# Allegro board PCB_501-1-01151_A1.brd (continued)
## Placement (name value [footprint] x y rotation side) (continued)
NOREF#809  -  []  20.17 22.21 0 top
NOREF#810  -  []  57.36 80.33 0 top
NOREF#811  -  []  78.21 22.1 0 top
NOREF#812  -  []  78.21 34.01 0 top
NOREF#813  -  []  78.85 64.66 0 top
NOREF#814  -  []  17.76 81.77 0 top
NOREF#815  -  []  14.08 74.55 0 top
NOREF#816  -  []  97.52 24.96 0 top
NOREF#817  -  []  29.82 76.73 0 top
NOREF#818  -  []  76.58 13.82 90 top
NOREF#819  -  []  50.78 66.44 0 top
NOREF#820  -  []  63.48 71.63 0 top
NOREF#821  -  []  96.9 42.91 90 top
NOREF#822  -  []  90.93 28.17 90 top
NOREF#823  -  []  6.22 53.6 90 top
NOREF#824  -  []  24.24 35.92 0 top
NOREF#825  -  []  36.81 49.93 0 top
NOREF#826  -  []  39.48 69.58 0 top
NOREF#827  -  []  9.02 46.49 90 top
NOREF#828  -  []  61.72 66.02 90 top
NOREF#829  -  []  36.94 20.46 0 top
NOREF#830  -  []  33.51 13.86 0 top
NOREF#831  -  []  73.41 13.82 90 top
NOREF#832  -  []  45.74 35.67 90 top
NOREF#833  -  []  7.35 46.21 0 top
NOREF#834  -  []  7.6 27.96 0 top
NOREF#835  -  []  9.02 44.94 90 top
NOREF#836  -  []  66.27 68.96 0 top
NOREF#837  -  []  67.07 30.71 90 top
NOREF#838  -  []  23.62 54.84 90 top
NOREF#839  -  []  58.27 44.72 0 top
NOREF#840  -  []  40.62 19.41 0 top
NOREF#841  -  []  52.43 40.11 0 top
NOREF#842  -  []  41.07 61.93 0 top
NOREF#843  -  []  63.48 70.49 0 top
NOREF#844  -  []  32.87 11.7 0 top
NOREF#845  -  []  33.51 17.8 0 top
NOREF#846  -  []  33.68 41.67 0 top
NOREF#847  -  []  21.23 39.73 0 top
NOREF#848  -  []  66.82 24.87 90 top
NOREF#849  -  []  22.46 40.64 0 top
NOREF#850  -  []  83.55 63.86 0 top
NOREF#851  -  []  4.04 48.12 0 top
NOREF#852  -  []  46.46 63.86 0 top
NOREF#853  -  []  51.9 2.33 0 top
NOREF#854  -  []  34.78 20.68 0 top
NOREF#855  -  []  18.75 86.98 90 top
NOREF#856  -  []  81.15 60.05 90 top
NOREF#857  -  []  83.42 68.05 0 top
NOREF#858  -  []  12.04 48.62 0 top
NOREF#859  -  []  66.15 53.11 0 top
NOREF#860  -  []  61.32 9.25 0 top
NOREF#861  -  []  38.1 10.9 90 top
NOREF#862  -  []  90.91 69.09 0 top
NOREF#863  -  []  41.38 10.78 0 top
NOREF#864  -  []  57.89 58.82 0 top
NOREF#865  -  []  77.41 33.01 0 top
NOREF#866  -  []  49.89 23.51 0 top
NOREF#867  -  []  9.89 45.86 0 top
NOREF#868  -  []  54.59 75.8 90 top
NOREF#869  -  []  94.47 83.55 0 top
NOREF#870  -  []  32.87 87.76 0 top
NOREF#871  -  []  62.97 42.16 0 top
NOREF#872  -  []  78.85 64.11 90 top
NOREF#873  -  []  2.27 48.75 0 top
NOREF#874  -  []  10.1 6.43 0 top
NOREF#875  -  []  60.98 46.97 0 top
NOREF#876  -  []  67.67 17.14 0 top
NOREF#877  -  []  77.7 27.16 0 top
NOREF#878  -  []  26.27 51.16 90 top
NOREF#879  -  []  51.41 38.12 0 top
NOREF#880  -  []  35.65 15.16 0 top
NOREF#881  -  []  51 -0.27 90 top
NOREF#882  -  []  83.97 25.41 0 top
NOREF#883  -  []  46.74 63.99 90 top
NOREF#884  -  []  60.38 50.58 90 top
NOREF#885  -  []  59.41 46.97 0 top
NOREF#886  -  []  86.72 28.05 0 top
NOREF#887  -  []  38.37 10.78 0 top
NOREF#888  -  []  94.63 68.94 90 top
NOREF#889  -  []  45.32 30.71 0 top
NOREF#890  -  []  67.91 46.5 0 top
NOREF#891  -  []  50.16 11.28 90 top
NOREF#892  -  []  63.36 71.35 90 top
NOREF#893  -  []  39.26 60.98 0 top
NOREF#894  -  []  58.44 58.82 0 top
NOREF#895  -  []  11.19 40.62 90 top
NOREF#896  -  []  41 59.73 0 top
NOREF#897  -  []  67.2 52.56 90 top
NOREF#898  -  []  72.64 10.01 90 top
NOREF#899  -  []  58.78 6.97 0 top
NOREF#900  -  []  26.27 49.64 0 top
NOREF#901  -  []  83.17 6.24 0 top
NOREF#902  -  []  30.72 39.39 0 top
NOREF#903  -  []  29.82 40.37 0 top
NOREF#904  -  []  33.51 14.71 0 top
NOREF#905  -  []  38.61 69.7 90 top
NOREF#906  -  []  83.55 63.86 90 top
NOREF#907  -  []  50.14 57.29 0 top
NOREF#908  -  []  46.34 18.65 0 top
NOREF#909  -  []  58.41 79.78 90 top
NOREF#910  -  []  29.82 41.42 0 top
NOREF#911  -  []  11.76 101 180 top
NOREF#912  -  []  67.67 26.29 0 top
NOREF#913  -  []  91.19 80.6 0 top
NOREF#914  -  []  49.13 49.28 0 top
NOREF#915  -  []  11.92 59.03 0 top
NOREF#916  -  []  66.37 69.09 90 top
NOREF#917  -  []  30.84 39.12 0 top
NOREF#918  -  []  35.93 83.33 90 top
NOREF#919  -  []  47.22 67.44 0 top
NOREF#920  -  []  59.48 49.02 0 top
NOREF#921  -  []  68.71 13.82 90 top
NOREF#922  -  []  96.79 99.77 0 top
NOREF#923  -  []  56.39 12.81 90 top
NOREF#924  -  []  68.33 75.29 90 top
NOREF#925  -  []  35.79 17.02 0 top
NOREF#926  -  []  81.41 9.63 90 top
NOREF#927  -  []  31.39 69.83 0 top
NOREF#928  -  []  35.67 39.65 0 top
NOREF#929  -  []  77.07 19.03 0 top
NOREF#930  -  []  9.55 41.77 0 top
NOREF#931  -  []  78.5 73.42 0 top
NOREF#932  -  []  -7.08 -7.08 90 top
NOREF#933  -  []  51.31 22.59 90 top
NOREF#934  -  []  56.62 51.58 0 top
NOREF#935  -  []  14.58 8.16 0 top
NOREF#936  -  []  48.28 74.28 0 top
NOREF#937  -  []  11.83 47.48 90 top
NOREF#938  -  []  93.85 52.94 90 top
NOREF#939  -  []  7.62 46.34 90 top
NOREF#940  -  []  52.81 49.26 0 top
NOREF#941  -  []  77.34 12.3 90 top
NOREF#942  -  []  89.92 24.62 90 top
NOREF#943  -  []  8.11 38.61 0 top
NOREF#944  -  []  58.78 8.02 0 top
NOREF#945  -  []  42.04 19.54 90 top
NOREF#946  -  []  46.95 68.81 0 top
NOREF#947  -  []  68.3 72.88 0 top
NOREF#948  -  []  23.75 45.7 90 top
NOREF#949  -  []  107.08 -7.08 90 top
NOREF#950  -  []  83.97 11.42 90 top
NOREF#951  -  []  48.37 28.94 0 top
NOREF#952  -  []  70.34 63.26 0 top
NOREF#953  -  []  67.55 22.58 0 top
NOREF#954  -  []  52.2 67.29 90 top
NOREF#955  -  []  51.92 67.17 0 top
NOREF#956  -  []  32.73 12.43 0 top
NOREF#957  -  []  76.71 57.75 90 top
NOREF#958  -  []  30.97 72.24 0 top
NOREF#959  -  []  65.68 47.48 90 top
NOREF#960  -  []  29.65 73.42 90 top
NOREF#961  -  []  93.69 67.56 0 top
NOREF#962  -  []  83.29 5.97 0 top
NOREF#963  -  []  63.48 16.11 0 top
NOREF#964  -  []  59.69 47.1 90 top
NOREF#965  -  []  54.21 67.04 0 top
NOREF#966  -  []  50.02 66.66 0 top
NOREF#967  -  []  60.66 50.46 0 top
NOREF#968  -  []  61.32 73.05 0 top
NOREF#969  -  []  93.08 88.6 0 top
NOREF#970  -  []  94.13 53.87 0 top
NOREF#971  -  []  78.1 13.82 90 top
NOREF#972  -  []  74.4 67.92 0 top
NOREF#973  -  []  51.79 28.94 0 top
NOREF#974  -  []  33.89 56.65 90 top
NOREF#975  -  []  51.16 35.16 0 top
NOREF#976  -  []  49.3 23.51 0 top
NOREF#977  -  []  50.14 56.24 0 top
NOREF#978  -  []  47.1 67.16 0 top
NOREF#979  -  []  51.03 11.16 0 top
NOREF#980  -  []  54.65 60.06 0 top
NOREF#981  -  []  78.76 15.48 0 top
NOREF#982  -  []  68.3 6.88 0 top
NOREF#983  -  []  35.94 94.47 90 top
NOREF#984  -  []  61.49 19.41 90 top
NOREF#985  -  []  31.73 49.81 0 top
NOREF#986  -  []  50.51 36.36 0 top
NOREF#987  -  []  84.44 -1 0 top
NOREF#988  -  []  90.91 25.54 0 top
NOREF#989  -  []  51.67 62.63 0 top
NOREF#990  -  []  44.81 12.57 0 top
NOREF#991  -  []  18.56 68.72 0 top
NOREF#992  -  []  67.55 16.87 0 top
NOREF#993  -  []  35.04 64.95 0 top
NOREF#994  -  []  66.42 45.07 90 top
NOREF#995  -  []  12.05 59.31 0 top
NOREF#996  -  []  57.68 44.05 0 top
NOREF#997  -  []  31.99 57.28 0 top
NOREF#998  -  []  45.32 65.51 0 top
NOREF#999  -  []  41.4 87.25 90 top
NOREF#1000  -  []  74.55 62.46 90 top
NOREF#1001  -  []  77.07 10.94 0 top
NOREF#1002  -  []  50.29 66.78 90 top
NOREF#1003  -  []  53.69 51.49 90 top
NOREF#1004  -  []  67.91 46.1 0 top
NOREF#1005  -  []  2.75 19.74 90 top
NOREF#1006  -  []  51.67 60.71 0 top
NOREF#1007  -  []  64.5 4.05 0 top
NOREF#1008  -  []  65.89 21.72 0 top
NOREF#1009  -  []  80.24 23 0 top
NOREF#1010  -  []  54.76 8.87 0 top
NOREF#1011  -  []  17.76 82.82 0 top
NOREF#1012  -  []  44.17 25.67 0 top
NOREF#1013  -  []  46.34 59.73 0 top
NOREF#1014  -  []  30.1 75.8 90 top
NOREF#1015  -  []  43.69 68.54 90 top
NOREF#1016  -  []  33.95 71.5 0 top
NOREF#1017  -  []  44.43 32.37 0 top
NOREF#1018  -  []  47.9 43.29 90 top
NOREF#1019  -  []  44.17 23.51 0 top
NOREF#1020  -  []  67.55 26.01 0 top
NOREF#1021  -  []  49 49 0 top
NOREF#1022  -  []  71.88 62.34 90 top
NOREF#1023  -  []  45.59 24.75 90 top
NOREF#1024  -  []  37.1 57.24 90 top
NOREF#1025  -  []  78.1 13.82 90 top
NOREF#1026  -  []  43.43 8.87 90 top
NOREF#1027  -  []  52.81 46.5 0 top
NOREF#1028  -  []  78.09 21.82 90 top
NOREF#1029  -  []  14.08 73.41 0 top
NOREF#1030  -  []  61 35.38 0 top
NOREF#1031  -  []  15.11 48.75 90 top
NOREF#1032  -  []  85.47 64.81 90 top
NOREF#1033  -  []  11.92 53.95 0 top
NOREF#1034  -  []  27.07 82.57 90 top
NOREF#1035  -  []  28.05 16.26 0 top
NOREF#1036  -  []  44.56 47.98 0 top
NOREF#1037  -  []  74.28 73.66 0 top
NOREF#1038  -  []  59.05 7.09 90 top
NOREF#1039  -  []  20.68 46.63 0 top
NOREF#1040  -  []  63.23 67.58 0 top
NOREF#1041  -  []  20.54 52.2 0 top
NOREF#1042  -  []  60.71 47.1 90 top
NOREF#1043  -  []  63.48 69.34 0 top
NOREF#1044  -  []  63.63 4.17 90 top
NOREF#1045  -  []  56.62 50.44 0 top
NOREF#1046  -  []  46.97 43.56 0 top
NOREF#1047  -  []  40.64 64.1 90 top
NOREF#1048  -  []  71.25 94.47 90 top
NOREF#1049  -  []  62.09 43.92 0 top
NOREF#1050  -  []  54.74 62.72 90 top
NOREF#1051  -  []  72.92 12.17 0 top
NOREF#1052  -  []  84.73 29.83 0 top
NOREF#1053  -  []  20.96 45.7 90 top
NOREF#1054  -  []  46.97 12.57 0 top
NOREF#1055  -  []  19.68 11.54 90 top
NOREF#1056  -  []  89.64 57.02 0 top
NOREF#1057  -  []  63.88 6.71 90 top
NOREF#1058  -  []  97.77 43.83 0 top
NOREF#1059  -  []  46.88 17.8 0 top
NOREF#1060  -  []  78.97 63.25 0 top
NOREF#1061  -  []  60.38 52.49 90 top
NOREF#1062  -  []  91.39 100 0 top
NOREF#1063  -  []  15.86 81.05 0 top
NOREF#1064  -  []  36.7 15.16 90 top
NOREF#1065  -  []  73.01 56.77 0 top
NOREF#1066  -  []  4.06 45.45 90 top
NOREF#1067  -  []  59.33 12.68 0 top
NOREF#1068  -  []  93.07 60.85 0 top
NOREF#1069  -  []  10.14 39.48 0 top
NOREF#1070  -  []  95.9 25.13 90 top
NOREF#1071  -  []  15.98 48.62 0 top
NOREF#1072  -  []  8.11 42.16 0 top
NOREF#1073  -  []  59.67 34 0 top
NOREF#1074  -  []  76.31 13.7 0 top
NOREF#1075  -  []  51.92 66.8 0 top
NOREF#1076  -  []  47.39 18.65 90 top
NOREF#1077  -  []  50.04 16.87 90 top
NOREF#1078  -  []  76.81 72.33 0 top
NOREF#1079  -  []  20.72 22.21 0 top
NOREF#1080  -  []  30.72 37.7 90 top
NOREF#1081  -  []  37.45 56.15 0 top
NOREF#1082  -  []  67.42 9.42 0 top
NOREF#1083  -  []  8.57 0.31 0 top
NOREF#1084  -  []  94.72 30.35 0 top
NOREF#1085  -  []  76.86 13.7 0 top
NOREF#1086  -  []  66.4 41.91 0 top
NOREF#1087  -  []  95.74 77.62 0 top
NOREF#1088  -  []  23.35 54.72 0 top
NOREF#1089  -  []  11.92 74.27 90 top
NOREF#1090  -  []  79.33 13.36 90 top
NOREF#1091  -  []  51.69 37.19 90 top
NOREF#1092  -  []  53.09 61.7 90 top
NOREF#1093  -  []  62.21 5.1 0 top
NOREF#1094  -  []  14.86 52.3 90 top
NOREF#1095  -  []  94.98 25.4 0 top
NOREF#1096  -  []  38.97 64.66 0 top
NOREF#1097  -  []  86 29.83 0 top
NOREF#1098  -  []  89.41 21.57 90 top
NOREF#1099  -  []  67.2 69.83 90 top
NOREF#1100  -  []  65.89 25.15 0 top
NOREF#1101  -  []  89.52 58.44 0 top
NOREF#1102  -  []  66.82 21.44 90 top
NOREF#1103  -  []  91.46 25.54 0 top
NOREF#1104  -  []  90.79 68.81 0 top
NOREF#1105  -  []  62.21 40.13 0 top
NOREF#1106  -  []  49.78 74.36 90 top
NOREF#1107  -  []  43.2 37.19 0 top
NOREF#1108  -  []  83.82 80.5 90 top
NOREF#1109  -  []  53.61 36.3 0 top
NOREF#1110  -  []  82.52 80.32 0 top
NOREF#1111  -  []  58.01 38.71 90 top
NOREF#1112  -  []  54.21 65.39 0 top
NOREF#1113  -  []  59.84 7.51 0 top
NOREF#1114  -  []  77.62 19.03 0 top
NOREF#1115  -  []  29.44 86.74 0 top
NOREF#1116  -  []  18.78 53.67 0 top
NOREF#1117  -  []  21.59 22.33 90 top
NOREF#1118  -  []  7.34 47.26 0 top
NOREF#1119  -  []  98.32 43.83 0 top
NOREF#1120  -  []  54.76 6.97 0 top
NOREF#1121  -  []  67.69 8.49 90 top
NOREF#1122  -  []  59.67 37.45 0 top
NOREF#1123  -  []  12.05 72.01 0 top
NOREF#1124  -  []  37.7 63.61 0 top
NOREF#1125  -  []  38.73 46.34 90 top
NOREF#1126  -  []  40.13 32.49 90 top
NOREF#1127  -  []  3.19 6.3 0 top
NOREF#1128  -  []  38.73 60.03 90 top
NOREF#1129  -  []  33.03 70.57 0 top
NOREF#1130  -  []  21.48 50.4 90 top
NOREF#1131  -  []  78.85 66.95 0 top
NOREF#1132  -  []  45.61 49.13 90 top
NOREF#1133  -  []  31.12 69.96 90 top
NOREF#1134  -  []  60.09 39.61 0 top
NOREF#1135  -  []  14.35 36.05 90 top
NOREF#1136  -  []  23.73 84.05 90 top
NOREF#1137  -  []  44.42 64.82 90 top
NOREF#1138  -  []  69.44 30.99 0 top
NOREF#1139  -  []  93.71 69.22 0 top
NOREF#1140  -  []  48.75 11.16 0 top
NOREF#1141  -  []  50.58 71.08 0 top
NOREF#1142  -  []  88.62 20.72 0 top
NOREF#1143  -  []  54.48 7.09 90 top
NOREF#1144  -  []  61.2 42.44 0 top
NOREF#1145  -  []  92.44 52.81 0 top
NOREF#1146  -  []  12.05 61.85 0 top
NOREF#1147  -  []  58.35 15.12 0 top
NOREF#1148  -  []  43.71 8.75 0 top
NOREF#1149  -  []  68.6 22.59 90 top
NOREF#1150  -  []  11.92 74.82 0 top
NOREF#1151  -  []  59.29 7.51 0 top
NOREF#1152  -  []  15.01 22.21 0 top
NOREF#1153  -  []  50.93 29.06 90 top
NOREF#1154  -  []  46.46 75.33 0 top
NOREF#1155  -  []  85.45 29.83 0 top
NOREF#1156  -  []  11.92 56.49 0 top
NOREF#1157  -  []  38.95 54.48 0 top
NOREF#1158  -  []  35.52 24.29 0 top
NOREF#1159  -  []  33.25 29.19 0 top
NOREF#1160  -  []  10.41 41.89 90 top
NOREF#1161  -  []  45.32 24.62 0 top
NOREF#1162  -  []  44.43 33.42 0 top
NOREF#1163  -  []  33.13 41.67 0 top
NOREF#1164  -  []  49.76 72.12 0 top
NOREF#1165  -  []  36.94 50.93 0 top
NOREF#1166  -  []  46.74 65.64 90 top
NOREF#1167  -  []  49.89 25.67 0 top
NOREF#1168  -  []  81.01 25.29 0 top
NOREF#1169  -  []  11.92 64.11 90 top
NOREF#1170  -  []  49.89 12.21 0 top
NOREF#1171  -  []  57.64 6.97 0 top
NOREF#1172  -  []  5.46 38.96 90 top
NOREF#1173  -  []  5.82 26.69 0 top
NOREF#1174  -  []  18.78 53.67 90 top
NOREF#1175  -  []  54.23 44.05 90 top
NOREF#1176  -  []  89.39 27.5 90 top
NOREF#1177  -  []  84.46 28.17 90 top
NOREF#1178  -  []  43.31 22.59 90 top
NOREF#1179  -  []  28.45 75.02 90 top
NOREF#1180  -  []  68.6 21.44 90 top
NOREF#1181  -  []  13.57 41.13 0 top
NOREF#1182  -  []  36.68 64.55 0 top
NOREF#1183  -  []  77.94 71.43 0 top
NOREF#1184  -  []  66.29 19.33 90 top
NOREF#1185  -  []  77.95 73.42 0 top
NOREF#1186  -  []  46.74 74.4 90 top
NOREF#1187  -  []  95.74 77.07 90 top
NOREF#1188  -  []  90.13 67.16 90 top
NOREF#1189  -  []  66.78 50.91 0 top
NOREF#1190  -  []  93.2 63.72 0 top
NOREF#1191  -  []  59.82 39.73 90 top
NOREF#1192  -  []  85.41 33.01 90 top
NOREF#1193  -  []  7.73 27.69 0 top
NOREF#1194  -  []  50.2 59.42 90 top
NOREF#1195  -  []  68.6 26.01 90 top
NOREF#1196  -  []  46.33 17.8 0 top
NOREF#1197  -  []  66.27 71.25 0 top
NOREF#1198  -  []  89.39 29.83 0 top
NOREF#1199  -  []  46.85 43.84 0 top
NOREF#1200  -  []  45.45 56.81 0 top
NOREF#1201  -  []  68.78 101 180 top
NOREF#1202  -  []  15.86 80.5 90 top
NOREF#1203  -  []  17.53 48.75 90 top
NOREF#1204  -  []  60.43 6.58 0 top
NOREF#1205  -  []  61.96 48.15 0 top
NOREF#1206  -  []  70.87 5.95 90 top
NOREF#1207  -  []  91.69 22.86 90 top
NOREF#1208  -  []  44.56 49.13 0 top
NOREF#1209  -  []  12.05 74.55 0 top
NOREF#1210  -  []  66.29 37.06 90 top
NOREF#1211  -  []  71.86 31.48 0 top
NOREF#1212  -  []  53.09 49.38 90 top
NOREF#1213  -  []  33.38 40.24 0 top
NOREF#1214  -  []  51 -1.82 90 top
NOREF#1215  -  []  2.75 22.34 90 top
NOREF#1216  -  []  44.81 19.79 90 top
NOREF#1217  -  []  6.32 86.11 0 top
NOREF#1218  -  []  57.4 44.18 90 top
NOREF#1219  -  []  34.69 35.2 0 top
NOREF#1220  -  []  40.24 10.78 0 top
NOREF#1221  -  []  94.49 59.92 90 top
NOREF#1222  -  []  91.42 87.39 0 top
NOREF#1223  -  []  79.88 25 90 top
NOREF#1224  -  []  17.02 67.8 90 top
NOREF#1225  -  []  33.38 40.24 90 top
NOREF#1226  -  []  90.66 29.83 0 top
NOREF#1227  -  []  84.61 34.01 90 top
NOREF#1228  -  []  53.34 65.51 90 top
NOREF#1229  -  []  73.51 59.58 0 top
NOREF#1230  -  []  17.38 76.09 0 top
NOREF#1231  -  []  37.49 21.45 0 top
NOREF#1232  -  []  77.09 71.41 90 top
NOREF#1233  -  []  94.36 70.34 90 top
NOREF#1234  -  []  45.59 65.64 90 top
NOREF#1235  -  []  11.92 64.66 0 top
NOREF#1236  -  []  52.07 29.06 90 top
NOREF#1237  -  []  52.45 11.28 90 top
NOREF#1238  -  []  33.8 27.29 0 top
NOREF#1239  -  []  77.62 10.94 0 top
NOREF#1240  -  []  60.07 34 90 top
NOREF#1241  -  []  83.29 8.27 0 top
NOREF#1242  -  []  55.13 59.71 90 top
NOREF#1243  -  []  51.1 53.05 0 top
NOREF#1244  -  []  34.68 85.33 0 top
NOREF#1245  -  []  3.32 48.75 90 top
NOREF#1246  -  []  92.82 12.28 0 top
NOREF#1247  -  []  92.3 78.11 0 top
NOREF#1248  -  []  56.5 67.92 90 top
NOREF#1249  -  []  93.83 54.74 0 top
NOREF#1250  -  []  43.16 8.75 0 top
NOREF#1251  -  []  93.08 88.6 0 top
NOREF#1252  -  []  101 91.41 90 top
NOREF#1253  -  []  7.22 42.82 0 top
NOREF#1254  -  []  0 19.47 90 top
NOREF#1255  -  []  24.52 26.67 90 top
NOREF#1256  -  []  51.83 69.08 90 top
NOREF#1257  -  []  94.21 58.42 0 top
NOREF#1258  -  []  37.57 60.98 0 top
NOREF#1259  -  []  45.61 47.99 90 top
NOREF#1260  -  []  4.34 46.37 0 top
NOREF#1261  -  []  46.34 58.13 90 top
NOREF#1262  -  []  45.32 29.99 0 top
NOREF#1263  -  []  78.85 65.26 90 top
NOREF#1264  -  []  48.6 59.82 0 top
NOREF#1265  -  []  67.2 34.78 90 top
NOREF#1266  -  []  22.46 36.97 0 top
NOREF#1267  -  []  87.86 70.61 0 top
NOREF#1268  -  []  59.54 43.54 0 top
NOREF#1269  -  []  10.78 48.75 0 top
NOREF#1270  -  []  34.29 10.78 90 top
NOREF#1271  -  []  44.22 10.78 0 top
NOREF#1272  -  []  11.45 48.62 0 top
NOREF#1273  -  []  94.85 25.12 0 top
NOREF#1274  -  []  27.79 17.38 0 top
NOREF#1275  -  []  82.64 80.04 0 top
NOREF#1276  -  []  67.84 39.48 0 top
NOREF#1277  -  []  35.4 25.16 0 top
NOREF#1278  -  []  5.95 26.42 0 top
NOREF#1279  -  []  58.9 15.12 0 top
NOREF#1280  -  []  53.95 49.26 0 top
NOREF#1281  -  []  90.91 70.23 0 top
NOREF#1282  -  []  56.5 66.78 0 top
NOREF#1283  -  []  43.29 32.37 0 top
NOREF#1284  -  []  81.05 15.48 0 top
NOREF#1285  -  []  56.66 12.68 0 top
NOREF#1286  -  []  74.4 70.99 0 top
NOREF#1287  -  []  33.78 12.93 90 top
NOREF#1288  -  []  34.67 60.05 90 top
NOREF#1289  -  []  48.9 16.87 90 top
NOREF#1290  -  []  49.89 24.62 0 top
NOREF#1291  -  []  84.18 29.83 0 top
NOREF#1292  -  []  41.93 10.78 0 top
NOREF#1293  -  []  79.01 18.65 0 top
NOREF#1294  -  []  70.97 95.39 0 top
NOREF#1295  -  []  22.75 55.77 0 top
NOREF#1296  -  []  84.46 29.95 90 top
NOREF#1297  -  []  37.48 62.95 90 top
NOREF#1298  -  []  73.41 13.82 90 top
NOREF#1299  -  []  43.94 45.3 90 top
NOREF#1300  -  []  87.86 28.05 0 top
NOREF#1301  -  []  55.63 65.51 90 top
NOREF#1302  -  []  11.19 39.48 90 top
NOREF#1303  -  []  85.45 27.5 0 top
NOREF#1304  -  []  52.81 62.63 0 top
NOREF#1305  -  []  61.45 66.95 0 top
NOREF#1306  -  []  101 64 90 top
NOREF#1307  -  []  41.09 56.73 90 top
NOREF#1308  -  []  79.5 4.17 90 top
NOREF#1309  -  []  67.44 5.95 90 top
NOREF#1310  -  []  13.95 73.68 0 top
NOREF#1311  -  []  50.65 82.61 0 top
NOREF#1312  -  []  46.95 69.22 0 top
NOREF#1313  -  []  46.46 25.67 0 top
NOREF#1314  -  []  20.43 50.4 0 top
NOREF#1315  -  []  11.18 48.75 90 top
NOREF#1316  -  []  94.34 61.83 0 top
NOREF#1317  -  []  0.64 36.51 0 top
NOREF#1318  -  []  75.33 13.7 0 top
NOREF#1319  -  []  31.86 49.53 0 top
NOREF#1320  -  []  66.27 52.83 0 top
NOREF#1321  -  []  93.58 53.87 0 top
NOREF#1322  -  []  53.34 29.06 90 top
NOREF#1323  -  []  65.64 51.96 0 top
NOREF#1324  -  []  62.21 44.2 0 top
NOREF#1325  -  []  40.24 11.83 0 top
NOREF#1326  -  []  71.61 63.26 0 top
NOREF#1327  -  []  73.17 32.87 90 top
NOREF#1328  -  []  11.92 61.57 90 top
NOREF#1329  -  []  62.48 10.9 90 top
NOREF#1330  -  []  63.35 62.74 0 top
NOREF#1331  -  []  50.06 49 90 top
NOREF#1332  -  []  42.8 10.9 90 top
NOREF#1333  -  []  27.05 90.91 90 top
NOREF#1334  -  []  74.57 10.94 0 top
NOREF#1335  -  []  72.64 58.65 90 top
NOREF#1336  -  []  74.83 72.41 0 top
NOREF#1337  -  []  5.7 50.42 0 top
NOREF#1338  -  []  71.12 12.3 90 top
NOREF#1339  -  []  53.85 23.35 90 top
NOREF#1340  -  []  64.28 62.46 90 top
NOREF#1341  -  []  23.22 90.44 0 top
NOREF#1342  -  []  51.67 61.58 0 top
NOREF#1343  -  []  32.76 46.3 90 top
NOREF#1344  -  []  70.84 12.17 0 top
NOREF#1345  -  []  78.36 4.17 90 top
NOREF#1346  -  []  65.77 20.3 0 top
NOREF#1347  -  []  7.98 38.33 0 top
NOREF#1348  -  []  5.24 37.06 90 top
NOREF#1349  -  []  76.58 13.82 90 top
NOREF#1350  -  []  76.43 25.38 0 top
NOREF#1351  -  []  94.09 58.7 0 top
NOREF#1352  -  []  66.02 17.14 0 top
NOREF#1353  -  []  32.62 35.2 0 top
NOREF#1354  -  []  67.56 39.6 90 top
NOREF#1355  -  []  59.96 46.97 0 top
NOREF#1356  -  []  36.82 68.62 90 top
NOREF#1357  -  []  47.9 12.3 90 top
NOREF#1358  -  []  37.08 62.95 90 top
NOREF#1359  -  []  76.71 25.51 90 top
NOREF#1360  -  []  24.24 36.97 0 top
NOREF#1361  -  []  76.2 19.16 90 top
NOREF#1362  -  []  56.5 49.38 0 top
NOREF#1363  -  []  67.67 24 0 top
NOREF#1364  -  []  66.95 16.87 90 top
NOREF#1365  -  []  35.29 28.87 90 top
NOREF#1366  -  []  64.77 4.17 90 top
NOREF#1367  -  []  33.95 71.5 0 top
NOREF#1368  -  []  76.71 27.29 90 top
NOREF#1369  -  []  73.13 13.7 0 top
NOREF#1370  -  []  23.86 85.6 0 top
NOREF#1371  -  []  71.61 13.7 0 top
NOREF#1372  -  []  52.81 50.31 0 top
NOREF#1373  -  []  67.67 19.43 0 top
NOREF#1374  -  []  94.6 31.22 0 top
NOREF#1375  -  []  22.14 51.8 90 top
NOREF#1376  -  []  95.14 57 90 top
NOREF#1377  -  []  35.04 62.05 90 top
NOREF#1378  -  []  68.6 28.3 90 top
NOREF#1379  -  []  106.17 104.5 0 top
NOREF#1380  -  []  68.58 5.95 90 top
NOREF#1381  -  []  51.29 56.24 0 top
NOREF#1382  -  []  72.92 59.58 0 top
NOREF#1383  -  []  31.1 72.52 0 top
NOREF#1384  -  []  35.4 24.01 90 top
NOREF#1385  -  []  36.45 25.16 90 top
NOREF#1386  -  []  11.92 69.19 0 top
NOREF#1387  -  []  31.73 37.96 0 top
NOREF#1388  -  []  75.54 12.17 0 top
NOREF#1389  -  []  67.16 6.88 0 top
NOREF#1390  -  []  12.34 43.67 90 top
NOREF#1391  -  []  51.4 83.85 0 top
NOREF#1392  -  []  50.65 29.99 0 top
NOREF#1393  -  []  74.28 69.45 90 top
NOREF#1394  -  []  57.04 7.09 0 top
NOREF#1395  -  []  55.35 8.87 0 top
NOREF#1396  -  []  18.16 71.62 90 top
NOREF#1397  -  []  57.39 6.2 0 top
NOREF#1398  -  []  52.81 45.45 0 top
NOREF#1399  -  []  69.07 9.29 0 top
NOREF#1400  -  []  35.4 24.56 0 top
NOREF#1401  -  []  78.85 67.54 90 top
NOREF#1402  -  []  62.25 41.89 90 top
NOREF#1403  -  []  65.89 24 0 top
NOREF#1404  -  []  42.18 48.4 0 top
NOREF#1405  -  []  38.33 61.63 0 top
NOREF#1406  -  []  75.06 13.82 90 top
NOREF#1407  -  []  37.36 50.65 0 top
NOREF#1408  -  []  73.01 82.61 0 top
NOREF#1409  -  []  38.95 54.08 90 top
NOREF#1410  -  []  66.15 49.76 90 top
NOREF#1411  -  []  78.85 66.4 90 top
NOREF#1412  -  []  53.57 23.22 0 top
NOREF#1413  -  []  77.7 28.21 0 top
NOREF#1414  -  []  45.32 66.57 0 top
NOREF#1415  -  []  42.91 56.3 0 top
NOREF#1416  -  []  76.37 23.22 0 top
NOREF#1417  -  []  57.3 58.82 0 top
NOREF#1418  -  []  46.46 23.51 0 top
NOREF#1419  -  []  21.31 22.21 0 top
NOREF#1420  -  []  35.52 25.43 0 top
NOREF#1421  -  []  52.81 43.92 0 top
NOREF#1422  -  []  62.09 39.86 90 top
NOREF#1423  -  []  32.87 89.03 0 top
NOREF#1424  -  []  65.77 22.58 0 top
NOREF#1425  -  []  55.63 9 90 top
NOREF#1426  -  []  20.68 45.58 0 top
NOREF#1427  -  []  89.14 81.05 0 top
NOREF#1428  -  []  78.85 65.81 0 top
NOREF#1429  -  []  87.74 70.34 0 top
NOREF#1430  -  []  44.94 10.8 0 top
NOREF#1431  -  []  66.82 20.3 90 top
NOREF#1432  -  []  67.55 19.16 0 top
NOREF#1433  -  []  32.93 71.6 0 top
NOREF#1434  -  []  76.43 26.43 0 top
NOREF#1435  -  []  67.2 68.69 90 top
NOREF#1436  -  []  14.31 38.86 0 top
NOREF#1437  -  []  56.62 50.8 0 top
NOREF#1438  -  []  33.53 27.41 90 top
NOREF#1439  -  []  42.14 32.37 0 top
NOREF#1440  -  []  51.33 66.44 0 top
NOREF#1441  -  []  78.49 15.6 90 top
NOREF#1442  -  []  68.05 75.17 0 top
NOREF#1443  -  []  28.93 84.64 0 top
NOREF#1444  -  []  94.12 81.26 90 top
NOREF#1445  -  []  79.36 12.72 0 top
NOREF#1446  -  []  80.52 22.08 90 top
NOREF#1447  -  []  44.81 10.52 0 top
NOREF#1448  -  []  81.32 84.2 0 top
NOREF#1449  -  []  23.73 85.32 0 top
NOREF#1450  -  []  47.01 65.16 0 top
NOREF#1451  -  []  51.58 11.16 0 top
NOREF#1452  -  []  12.97 53.95 90 top
NOREF#1453  -  []  67.2 70.97 90 top
NOREF#1454  -  []  28.85 75.02 0 top
NOREF#1455  -  []  72.12 33.42 0 top
NOREF#1456  -  []  53.85 25.51 90 top
NOREF#1457  -  []  20.68 39.73 0 top
NOREF#1458  -  []  85.48 70.29 0 top
NOREF#1459  -  []  18.16 71.62 90 top
NOREF#1460  -  []  65 53.45 0 top
NOREF#1461  -  []  42.93 37.32 90 top
NOREF#1462  -  []  78.97 67.82 0 top
NOREF#1463  -  []  2.79 39.06 90 top
NOREF#1464  -  []  79.74 60.98 0 top
NOREF#1465  -  []  99.71 105.06 0 top
NOREF#1466  -  []  14.56 38.23 0 top
NOREF#1467  -  []  52.61 69.89 0 top
NOREF#1468  -  []  23.39 40.37 90 top
NOREF#1469  -  []  63.23 62.46 0 top
NOREF#1470  -  []  18.05 11.41 0 top
NOREF#1471  -  []  77.83 13.7 0 top
NOREF#1472  -  []  79.74 57.53 0 top
NOREF#1473  -  []  70.59 6.88 0 top
NOREF#1474  -  []  59.56 4.93 90 top
NOREF#1475  -  []  33.51 15.77 0 top
NOREF#1476  -  []  33.4 40.75 90 top
NOREF#1477  -  []  62.23 54.84 90 top
NOREF#1478  -  []  59.56 6.58 90 top
NOREF#1479  -  []  28.05 41.67 0 top
NOREF#1480  -  []  76.31 74.11 0 top
NOREF#1481  -  []  67.17 26.9 90 top
NOREF#1482  -  []  80.16 24.87 0 top
NOREF#1483  -  []  31.77 38.84 90 top
NOREF#1484  -  []  22.2 55.77 0 top
NOREF#1485  -  []  22.1 45.7 90 top
NOREF#1486  -  []  49.3 11.16 0 top
NOREF#1487  -  []  47.77 29.06 90 top
NOREF#1488  -  []  73.13 14.75 0 top
NOREF#1489  -  []  14.84 49.67 0 top
NOREF#1490  -  []  58.78 12.68 0 top
NOREF#1491  -  []  13.32 81.11 90 top
NOREF#1492  -  []  39.48 70.63 0 top
NOREF#1493  -  []  61.43 18.38 0 top
NOREF#1494  -  []  56.97 41.21 0 top
NOREF#1495  -  []  64.28 63.61 90 top
NOREF#1496  -  []  17.78 11.54 90 top
NOREF#1497  -  []  13.7 41.4 0 top
NOREF#1498  -  []  54.72 76.07 0 top
NOREF#1499  -  []  46.46 65.51 0 top
NOREF#1500  -  []  39.91 63.92 0 top
NOREF#1501  -  []  46.46 18.92 0 top
NOREF#1502  -  []  15.13 53.23 0 top
NOREF#1503  -  []  97.39 38.5 0 top
NOREF#1504  -  []  26.14 82.3 0 top
NOREF#1505  -  []  85.72 28.17 90 top
NOREF#1506  -  []  51.89 70.49 90 top
NOREF#1507  -  []  27.33 91.84 0 top
NOREF#1508  -  []  49.51 29.99 0 top
NOREF#1509  -  []  79.9 15.48 0 top
NOREF#1510  -  []  42.31 22.24 0 top
NOREF#1511  -  []  78.08 5.1 0 top
NOREF#1512  -  []  77.62 12.17 0 top
NOREF#1513  -  []  46.85 12.85 0 top
NOREF#1514  -  []  23.5 29.21 90 top
NOREF#1515  -  []  12.97 69.19 90 top
NOREF#1516  -  []  50.16 24.75 90 top
NOREF#1517  -  []  16.74 68.72 0 top
NOREF#1518  -  []  78.08 4.05 0 top
NOREF#1519  -  []  80.77 15.6 90 top
NOREF#1520  -  []  32.75 87.48 0 top
NOREF#1521  -  []  66.15 69.24 0 top
NOREF#1522  -  []  39.21 67.42 0 top
NOREF#1523  -  []  39.1 11.83 0 top
NOREF#1524  -  []  51.02 58.78 0 top
NOREF#1525  -  []  20.05 43.56 0 top
NOREF#1526  -  []  94.76 60.85 0 top
NOREF#1527  -  []  79.46 13.64 0 top
NOREF#1528  -  []  55.35 65.39 0 top
NOREF#1529  -  []  32.75 89.9 90 top
NOREF#1530  -  []  15.36 92.42 0 top
NOREF#1531  -  []  92.73 86.88 90 top
NOREF#1532  -  []  53.3 53.05 90 top
NOREF#1533  -  []  29.82 75.67 0 top
NOREF#1534  -  []  65.36 19.61 0 top
NOREF#1535  -  []  57.13 44.05 0 top
NOREF#1536  -  []  68.98 13.7 0 top
NOREF#1537  -  []  44.94 75.35 90 top
NOREF#1538  -  []  54.23 49.38 90 top
NOREF#1539  -  []  44.68 49.4 0 top
NOREF#1540  -  []  69.07 9.89 0 top
NOREF#1541  -  []  53.87 11.16 0 top
NOREF#1542  -  []  14.58 53.23 0 top
NOREF#1543  -  []  52.61 16.76 90 top
NOREF#1544  -  []  30.84 37.97 0 top
NOREF#1545  -  []  65.77 21.44 0 top
NOREF#1546  -  []  52.79 57.53 0 top
NOREF#1547  -  []  50.04 72.24 90 top
NOREF#1548  -  []  21.86 22.21 0 top
NOREF#1549  -  []  68.6 24.87 90 top
NOREF#1550  -  []  51.56 56.37 90 top
NOREF#1551  -  []  11.29 43.67 0 top
NOREF#1552  -  []  35.31 83.43 90 top
NOREF#1553  -  []  69.47 62.34 90 top
NOREF#1554  -  []  47.01 23.51 0 top
NOREF#1555  -  []  39.75 69.7 90 top
NOREF#1556  -  []  69.26 31.58 0 top
NOREF#1557  -  []  69.87 12.3 0 top
NOREF#1558  -  []  17.8 48.62 0 top
NOREF#1559  -  []  90.13 67.56 0 top
NOREF#1560  -  []  23.73 84.6 0 top
NOREF#1561  -  []  44.81 33.53 0 top
NOREF#1562  -  []  27.92 15.98 90 top
NOREF#1563  -  []  93.45 68.3 0 top
NOREF#1564  -  []  14.73 22.33 90 top
NOREF#1565  -  []  12.97 59.03 90 top
NOREF#1566  -  []  65.89 20.57 0 top
NOREF#1567  -  []  54.21 68.09 0 top
NOREF#1568  -  []  44.17 65.51 0 top
NOREF#1569  -  []  8.78 30.08 0 top
NOREF#1570  -  []  94.6 30.08 0 top
NOREF#1571  -  []  60.73 18.15 0 top
NOREF#1572  -  []  73.01 82.61 90 top
NOREF#1573  -  []  74.28 70.72 0 top
NOREF#1574  -  []  70 6.88 0 top
NOREF#1575  -  []  65.9 16.87 0 top
NOREF#1576  -  []  35.77 15.43 0 top
NOREF#1577  -  []  81.51 7.37 0 top
NOREF#1578  -  []  91.21 29.83 0 top
NOREF#1579  -  []  63.9 41.89 90 top
NOREF#1580  -  []  76.1 23.35 90 top
NOREF#1581  -  []  54.48 9 90 top
NOREF#1582  -  []  69.07 10.94 0 top
NOREF#1583  -  []  10.27 39.75 0 top
NOREF#1584  -  []  83.89 65.8 90 top
NOREF#1585  -  []  56.87 40.92 0 top
NOREF#1586  -  []  60.11 53.41 0 top
NOREF#1587  -  []  51.05 65.51 90 top
NOREF#1588  -  []  53.07 65.39 0 top
NOREF#1589  -  []  72.64 12.3 90 top
NOREF#1590  -  []  75.92 19.03 0 top
NOREF#1591  -  []  88.14 28.17 90 top
NOREF#1592  -  []  51.92 66.44 0 top
NOREF#1593  -  []  96.76 19.44 90 top
NOREF#1594  -  []  10.9 49.02 0 top
NOREF#1595  -  []  77.83 14.75 0 top
NOREF#1596  -  []  63.48 17.16 0 top
NOREF#1597  -  []  56.49 7.09 0 top
NOREF#1598  -  []  11.92 62.12 0 top
NOREF#1599  -  []  2.39 49.02 0 top
NOREF#1600  -  []  51.56 35.81 90 top
NOREF#1601  -  []  79.99 10.56 0 top
NOREF#1602  -  []  34.02 10.65 0 top
NOREF#1603  -  []  62.76 10.78 0 top
NOREF#1604  -  []  47.6 24.62 0 top
NOREF#1605  -  []  23.47 46.63 0 top
NOREF#1606  -  []  41 32.37 0 top
NOREF#1607  -  []  84.36 47.44 0 top
NOREF#1608  -  []  89.52 57.3 0 top
NOREF#1609  -  []  14.08 35.92 0 top
NOREF#1610  -  []  61.54 38.03 0 top
NOREF#1611  -  []  62.97 9.25 0 top
NOREF#1612  -  []  73.75 89.53 90 top
NOREF#1613  -  []  77.34 19.16 90 top
NOREF#1614  -  []  37.7 64.66 0 top
NOREF#1615  -  []  76.81 71.28 0 top
NOREF#1616  -  []  77.07 12.17 0 top
NOREF#1617  -  []  47.06 65.79 0 top
NOREF#1618  -  []  67.67 28.58 0 top
NOREF#1619  -  []  61.21 41.24 0 top
NOREF#1620  -  []  71.86 32.53 0 top
NOREF#1621  -  []  10.14 42.82 0 top
NOREF#1622  -  []  50.31 17.8 0 top
NOREF#1623  -  []  33.51 18.65 0 top
NOREF#1624  -  []  34.4 59.93 0 top
NOREF#1625  -  []  74.15 73.39 0 top
NOREF#1626  -  []  49.78 29.06 90 top
NOREF#1627  -  []  90.46 23.59 0 top
NOREF#1628  -  []  71.88 13.82 90 top
NOREF#1629  -  []  65.8 35.54 90 top
NOREF#1630  -  []  67.55 21.44 0 top
NOREF#1631  -  []  2.79 36.96 90 top
NOREF#1632  -  []  5.57 50.14 90 top
NOREF#1633  -  []  48.37 29.99 0 top
NOREF#1634  -  []  42.31 20.46 0 top
NOREF#1635  -  []  7.6 29.36 0 top
NOREF#1636  -  []  91.19 20.68 90 top
NOREF#1637  -  []  51.58 23.51 0 top
NOREF#1638  -  []  67.67 22.86 0 top
NOREF#1639  -  []  30.84 36.83 0 top
NOREF#1640  -  []  12.97 71.73 90 top
NOREF#1641  -  []  95.29 67.16 90 top
NOREF#1642  -  []  73.75 83.85 0 top
NOREF#1643  -  []  10.14 41.77 0 top
NOREF#1644  -  []  32.86 43.97 90 top
NOREF#1645  -  []  94.6 31.22 90 top
NOREF#1646  -  []  63.01 47.6 90 top
NOREF#1647  -  []  32.78 49.25 90 top
NOREF#1648  -  []  67.67 27.43 0 top
NOREF#1649  -  []  12.32 48.75 90 top
NOREF#1650  -  []  83.69 68.18 90 top
NOREF#1651  -  []  57.33 40.07 90 top
NOREF#1652  -  []  55.35 7.09 0 top
NOREF#1653  -  []  33.53 25.63 90 top
NOREF#1654  -  []  30.72 37.7 0 top
NOREF#1655  -  []  36.72 40.24 90 top
NOREF#1656  -  []  75.09 27.18 90 top
NOREF#1657  -  []  81.39 7.09 90 top
NOREF#1658  -  []  55.13 59.71 0 top
NOREF#1659  -  []  57.02 65.51 90 top
NOREF#1660  -  []  57.02 57.89 90 top
NOREF#1661  -  []  90.97 80.4 0 top
NOREF#1662  -  []  53.32 11.16 0 top
NOREF#1663  -  []  73.97 27.89 0 top
NOREF#1664  -  []  38.12 60.98 0 top
NOREF#1665  -  []  68.6 27.16 90 top
NOREF#1666  -  []  28.07 17.51 90 top
NOREF#1667  -  []  60.43 19.96 0 top
NOREF#1668  -  []  74.27 63.39 0 top
NOREF#1669  -  []  67.16 5.82 0 top
NOREF#1670  -  []  10.54 53.15 90 top
NOREF#1671  -  []  79.48 12.45 0 top
NOREF#1672  -  []  41.63 48.4 0 top
NOREF#1673  -  []  77.45 23.48 0 top
NOREF#1674  -  []  34.91 20.96 0 top
NOREF#1675  -  []  56.75 66.44 0 top
NOREF#1676  -  []  91.04 83.08 0 top
NOREF#1677  -  []  69.83 72.88 0 top
NOREF#1678  -  []  30.2 84.09 0 top
NOREF#1679  -  []  93.06 100.21 0 top
NOREF#1680  -  []  62.85 42.44 0 top
NOREF#1681  -  []  33.38 39.65 0 top
NOREF#1682  -  []  33.38 84.35 0 top
NOREF#1683  -  []  20.43 48.62 0 top
NOREF#1684  -  []  76.31 57.75 90 top
NOREF#1685  -  []  50.63 36.09 0 top
NOREF#1686  -  []  40.46 63.64 0 top
NOREF#1687  -  []  26.27 49.64 90 top
NOREF#1688  -  []  89.77 20.72 0 top
NOREF#1689  -  []  76.56 21.06 0 top
NOREF#1690  -  []  31.34 -1 0 top
NOREF#1691  -  []  58.44 6.2 90 top
NOREF#1692  -  []  36.22 95.39 0 top
NOREF#1693  -  []  -1 78.29 270 top
NOREF#1694  -  []  -1 8.08 270 top
NOREF#1695  -  []  26.89 6.43 90 top
NOREF#1696  -  []  77.34 15.6 90 top
NOREF#1697  -  []  67.55 28.3 0 top
NOREF#1698  -  []  66.7 39.48 0 top
NOREF#1699  -  []  33.51 19.7 0 top
NOREF#1700  -  []  76.82 84.2 0 top
NOREF#1701  -  []  16.26 48.75 90 top
NOREF#1702  -  []  55.01 63.64 0 top
NOREF#1703  -  []  79.61 19.7 0 top
NOREF#1704  -  []  48.75 23.51 0 top
NOREF#1705  -  []  66.15 43.96 0 top
NOREF#1706  -  []  16.41 92.42 90 top
NOREF#1707  -  []  7.98 37.19 0 top
NOREF#1708  -  []  72.37 10.94 0 top
NOREF#1709  -  []  61.87 9.25 0 top
NOREF#1710  -  []  36.72 16.74 90 top
NOREF#1711  -  []  51.41 37.07 0 top
NOREF#1712  -  []  52.18 11.16 0 top
NOREF#1713  -  []  87.74 70.34 90 top
NOREF#1714  -  []  71.61 62.21 0 top
NOREF#1715  -  []  41.07 55.93 90 top
NOREF#1716  -  []  53.57 41.17 0 top
NOREF#1717  -  []  39.1 62.59 90 top
NOREF#1718  -  []  30.84 69.83 0 top
NOREF#1719  -  []  52.99 51.69 0 top
NOREF#1720  -  []  0.03 36.33 0 top
NOREF#1721  -  []  5.6 19.74 90 top
NOREF#1722  -  []  43.89 75.9 0 top
NOREF#1723  -  []  28.93 84.09 90 top
NOREF#1724  -  []  12.21 45.95 90 top
NOREF#1725  -  []  80.47 21.39 90 top
NOREF#1726  -  []  17.65 75.16 90 top
NOREF#1727  -  []  34.78 20.68 90 top
NOREF#1728  -  []  93.6 60.16 0 top
NOREF#1729  -  []  51.16 74.31 90 top
NOREF#1730  -  []  93.45 71.39 0 top
NOREF#1731  -  []  45.59 22.59 90 top
NOREF#1732  -  []  53.06 66.44 0 top
NOREF#1733  -  []  33.66 83.42 90 top
NOREF#1734  -  []  10.9 48.62 0 top
NOREF#1735  -  []  66.37 65.59 0 top
NOREF#1736  -  []  53.8 35.38 0 top
NOREF#1737  -  []  71.26 32.66 90 top
NOREF#1738  -  []  67.33 41.63 90 top
NOREF#1739  -  []  81.68 9.51 0 top
NOREF#1740  -  []  91.92 22.63 90 top
NOREF#1741  -  []  18.29 67.8 90 top
NOREF#1742  -  []  5.57 50.14 0 top
NOREF#1743  -  []  33.53 29.32 90 top
NOREF#1744  -  []  94.47 18.14 0 top
NOREF#1745  -  []  88.63 19.67 0 top
NOREF#1746  -  []  30.59 39.01 0 top
NOREF#1747  -  []  2.52 46.37 0 top
NOREF#1748  -  []  91.97 87.39 0 top
NOREF#1749  -  []  34.14 35.2 0 top
NOREF#1750  -  []  90.66 27.5 0 top
NOREF#1751  -  []  84.18 27.5 0 top
NOREF#1752  -  []  50.57 51.69 0 top
NOREF#1753  -  []  43.29 70.14 0 top
NOREF#1754  -  []  77.34 10.01 90 top
NOREF#1755  -  []  80.24 21.95 0 top
NOREF#1756  -  []  83.97 68.05 0 top
NOREF#1757  -  []  63.35 4.05 0 top
NOREF#1758  -  []  29.32 87.02 0 top
NOREF#1759  -  []  56.97 84.2 0 top
NOREF#1760  -  []  70.97 59.58 0 top
NOREF#1761  -  []  79.27 9.51 0 top
NOREF#1762  -  []  89.94 29.83 0 top
NOREF#1763  -  []  24.61 91.69 0 top
NOREF#1764  -  []  61.45 70.21 90 top
NOREF#1765  -  []  88.37 71.74 0 top
NOREF#1766  -  []  64.75 47.75 0 top
NOREF#1767  -  []  63.35 66.17 0 top
NOREF#1768  -  []  94.74 83.67 90 top
NOREF#1769  -  []  11.16 45.95 0 top
NOREF#1770  -  []  66.42 43.03 90 top
NOREF#1771  -  []  90.97 80.4 90 top
NOREF#1772  -  []  61.32 42.16 0 top
NOREF#1773  -  []  56.5 50.53 0 top
NOREF#1774  -  []  12.05 64.39 0 top
NOREF#1775  -  []  6.88 26.14 90 top
NOREF#1776  -  []  62.48 4.17 90 top
NOREF#1777  -  []  36.34 27.6 90 top
NOREF#1778  -  []  46.61 16.87 90 top
NOREF#1779  -  []  56.62 49.89 90 top
NOREF#1780  -  []  45.45 30.99 0 top
NOREF#1781  -  []  51.03 23.51 0 top
NOREF#1782  -  []  54.21 8.87 0 top
NOREF#1783  -  []  21.82 46.63 0 top
NOREF#1784  -  []  42.4 64.03 0 top
NOREF#1785  -  []  7.33 43.96 0 top
NOREF#1786  -  []  53.95 43.92 0 top
NOREF#1787  -  []  93.62 23.09 90 top
NOREF#1788  -  []  62.29 38.78 0 top
NOREF#1789  -  []  41.27 32.49 90 top
NOREF#1790  -  []  39.86 32.37 0 top
NOREF#1791  -  []  45.74 12.3 90 top
NOREF#1792  -  []  17.02 55.35 90 top
NOREF#1793  -  []  65.55 53.45 0 top
NOREF#1794  -  []  45.85 55.21 90 top
NOREF#1795  -  []  32.86 32.75 0 top
NOREF#1796  -  []  15.47 41.4 0 top
NOREF#1797  -  []  52.61 69.89 90 top
NOREF#1798  -  []  71.25 58.65 90 top
NOREF#1799  -  []  53.57 26.43 0 top
NOREF#1800  -  []  69.6 12.43 90 top
NOREF#1801  -  []  94.21 60.85 0 top
NOREF#1802  -  []  37.57 55.88 0 top
NOREF#1803  -  []  50.31 72.12 0 top
NOREF#1804  -  []  67.67 21.72 0 top
NOREF#1805  -  []  93.2 81.53 0 top
NOREF#1806  -  []  67.18 62.34 90 top
NOREF#1807  -  []  23.35 55.77 0 top
NOREF#1808  -  []  68.43 13.7 0 top
NOREF#1809  -  []  30.86 38.08 90 top
NOREF#1810  -  []  67.67 20.57 0 top
NOREF#1811  -  []  34.4 60.98 0 top
NOREF#1812  -  []  61.6 9.38 90 top
NOREF#1813  -  []  35.79 39.37 0 top
NOREF#1814  -  []  31.89 56.65 0 top
NOREF#1815  -  []  65.28 53.57 90 top
NOREF#1816  -  []  62.09 43.92 90 top
NOREF#1817  -  []  54.97 20.3 0 top
NOREF#1818  -  []  15.98 49.67 0 top
NOREF#1819  -  []  51.89 70.49 0 top
NOREF#1820  -  []  83.89 67.4 0 top
NOREF#1821  -  []  89.77 19.67 0 top
NOREF#1822  -  []  66.27 50.04 0 top
NOREF#1823  -  []  33.8 29.19 0 top
NOREF#1824  -  []  57.91 7.09 90 top
NOREF#1825  -  []  68.6 19.16 90 top
NOREF#1826  -  []  40.86 62.04 90 top
NOREF#1827  -  []  63.23 65.89 0 top
NOREF#1828  -  []  27.92 15.98 0 top
NOREF#1829  -  []  36.93 4.58 0 top
NOREF#1830  -  []  5.24 43.46 90 top
NOREF#1831  -  []  35.41 29.15 0 top
NOREF#1832  -  []  89.13 21.45 0 top
NOREF#1833  -  []  72.52 73.01 90 top
NOREF#1834  -  []  90.19 25.54 0 top
NOREF#1835  -  []  73.68 13.7 0 top
NOREF#1836  -  []  74.4 66.78 0 top
NOREF#1837  -  []  50.65 31.77 0 top
NOREF#1838  -  []  83.67 64.13 0 top
NOREF#1839  -  []  61.45 70.76 0 top
NOREF#1840  -  []  68.05 62.21 0 top
NOREF#1841  -  []  79.88 18.78 90 top
NOREF#1842  -  []  97.66 37.57 90 top
NOREF#1843  -  []  92.57 23.09 0 top
NOREF#1844  -  []  8.74 44.81 0 top
NOREF#1845  -  []  8.62 46.44 0 top
NOREF#1846  -  []  76.43 28.21 0 top
NOREF#1847  -  []  112.39 62.91 0 top
NOREF#1848  -  []  78.22 72.5 90 top
NOREF#1849  -  []  49.51 28.94 0 top
NOREF#1850  -  []  50.65 30.72 0 top
NOREF#1851  -  []  63.61 7.64 0 top
NOREF#1852  -  []  45.74 34.52 90 top
NOREF#1853  -  []  5.46 39.61 90 top
NOREF#1854  -  []  23.5 89.52 90 top
NOREF#1855  -  []  95.14 58.14 90 top
NOREF#1856  -  []  53.36 62.63 0 top
NOREF#1857  -  []  11.92 51.41 0 top
NOREF#1858  -  []  38.97 63.61 0 top
NOREF#1859  -  []  53.59 11.28 90 top
NOREF#1860  -  []  69.07 8.24 0 top
NOREF#1861  -  []  49.02 24.75 90 top
NOREF#1862  -  []  54.97 20.3 90 top
NOREF#1863  -  []  61.95 54.72 0 top
NOREF#1864  -  []  8.23 30.08 0 top
NOREF#1865  -  []  73.75 83.85 90 top
NOREF#1866  -  []  43.31 54.7 90 top
NOREF#1867  -  []  50.42 56.37 90 top
NOREF#1868  -  []  14.84 77.16 90 top
NOREF#1869  -  []  9.99 40.78 0 top
NOREF#1870  -  []  31.77 36.55 90 top
NOREF#1871  -  []  75.82 10.01 90 top
NOREF#1872  -  []  94.21 57.28 0 top
NOREF#1873  -  []  36.82 68.62 90 top
NOREF#1874  -  []  10.78 47.48 0 top
NOREF#1875  -  []  54.1 45.57 90 top
NOREF#1876  -  []  73.53 64.88 90 top
NOREF#1877  -  []  11.83 48.75 90 top
NOREF#1878  -  []  33.78 18.78 90 top
NOREF#1879  -  []  60.56 6.86 0 top
NOREF#1880  -  []  52.88 17.69 0 top
NOREF#1881  -  []  63.35 5.1 0 top
NOREF#1882  -  []  59.94 37.57 90 top
NOREF#1883  -  []  30.37 86.47 90 top
NOREF#1884  -  []  38.71 32.37 0 top
NOREF#1885  -  []  70.88 60.69 90 top
NOREF#1886  -  []  8.51 30.21 90 top
NOREF#1887  -  []  66.15 49.76 0 top
NOREF#1888  -  []  56.77 7.22 90 top
NOREF#1889  -  []  26.02 82.02 0 top
NOREF#1890  -  []  44.81 34.8 0 top
NOREF#1891  -  []  38.71 33.42 0 top
NOREF#1892  -  []  23.47 45.58 0 top
NOREF#1893  -  []  46.74 24.75 90 top
NOREF#1894  -  []  93.58 69.49 0 top
NOREF#1895  -  []  90.79 69.96 90 top
NOREF#1896  -  []  91.17 82.8 0 top
NOREF#1897  -  []  36.81 49.38 90 top
NOREF#1898  -  []  24.67 92.09 0 top
NOREF#1899  -  []  51 -1.82 0 top
NOREF#1900  -  []  63.25 9.38 90 top
NOREF#1901  -  []  75.6 2.33 90 top
NOREF#1902  -  []  128.05 80.25 0 top
NOREF#1903  -  []  63.36 69.07 90 top
NOREF#1904  -  []  -7.08 -7.08 0 top
NOREF#1905  -  []  17.02 53.7 90 top
NOREF#1906  -  []  56.77 9 90 top
NOREF#1907  -  []  22.48 54.84 90 top
NOREF#1908  -  []  50.33 47.48 90 top
NOREF#1909  -  []  12.05 56.77 0 top
NOREF#1910  -  []  53.1 50.14 90 top
NOREF#1911  -  []  32.75 88.75 0 top
NOREF#1912  -  []  57.51 5.33 0 top
NOREF#1913  -  []  95.52 18.14 90 top
NOREF#1914  -  []  39.24 63.73 90 top
NOREF#1915  -  []  40.89 19.54 90 top
NOREF#1916  -  []  45.74 33.25 90 top
NOREF#1917  -  []  43.03 23.51 0 top
NOREF#1918  -  []  66.53 13.6 90 top
NOREF#1919  -  []  63.36 70.21 0 top
NOREF#1920  -  []  65.77 23.73 0 top
NOREF#1921  -  []  89.13 22.5 0 top
NOREF#1922  -  []  70.38 72.88 0 top
NOREF#1923  -  []  90.17 94.21 90 top
NOREF#1924  -  []  83.57 79.77 90 top
NOREF#1925  -  []  32.89 34.27 90 top
NOREF#1926  -  []  17.5 11.41 0 top
NOREF#1927  -  []  93.07 59.8 0 top
NOREF#1928  -  []  51.29 57.29 0 top
NOREF#1929  -  []  53.09 45.57 90 top
NOREF#1930  -  []  38.99 60.05 90 top
NOREF#1931  -  []  67.82 94.47 90 top
NOREF#1932  -  []  67.33 50.91 0 top
NOREF#1933  -  []  5.32 90.61 90 top
NOREF#1934  -  []  40.51 10.9 90 top
NOREF#1935  -  []  59.82 43.67 90 top
NOREF#1936  -  []  5.3 24.77 0 top
NOREF#1937  -  []  91.84 101 180 top
NOREF#1938  -  []  48.77 94.34 90 top
NOREF#1939  -  []  59.54 44.59 0 top
NOREF#1940  -  []  51.88 68.45 0 top
NOREF#1941  -  []  75.82 23.22 0 top
NOREF#1942  -  []  35.67 17.89 90 top
NOREF#1943  -  []  32.9 33.15 0 top
NOREF#1944  -  []  89.66 28.17 90 top
NOREF#1945  -  []  70.89 63.26 0 top
P1  ESD8472MUT5G  [DIO-0201]  19.56 81.03 0 top
P2  ESD8472MUT5G  [DIO-0201]  81.03 19.3 90 bottom
P3  ESD8472MUT5G  [DIO-0201]  91.06 26.54 270 bottom
P4  ESD8472MUT5G  [DIO-0201]  89.66 26.54 270 bottom
P5  ESD8472MUT5G  [DIO-0201]  88.39 26.54 270 bottom
P6  ESD8472MUT5G  [DIO-0201]  87 26.54 270 bottom
P7  ESD8472MUT5G  [DIO-0201]  85.72 26.54 270 bottom
P8  ESD8472MUT5G  [DIO-0201]  84.33 26.54 270 bottom
P9  ESD8472MUT5G  [DIO-0201]  92.58 85.85 180 bottom
P10  ESD8472MUT5G  [DIO-0201]  83.33 78.76 0 bottom
P11  ESD8472MUT5G  [DIO-0201]  60.94 78.82 0 bottom
P12  ESD8472MUT5G  [DIO-0201]  58.02 78.82 0 bottom
P13  ESD8472MUT5G  [DIO-0201]  46.48 76.2 0 bottom
P14  ESD8472MUT5G  [DIO-0201]  47.16 83.5 90 top
P15  ESD8472MUT5G  [DIO-0201]  47.16 84.97 270 top
Q1  SSM6J501NU  [UDFN-6L_0P65_2X2_EP]  21.84 81.91 90 top
Q2  MMBT2907A  [SOT23-3L_1P9_3P12X1P5]  26.16 88.39 180 top
Q3  2N7002L  [SOT23-3L_1P9_2P9X1P3]  13.84 78.1 90 top
Q4  CSD25481F4  [MOSFET_0402-3L_A1]  60.96 5.33 180 top
Q5  CSD25481F4  [MOSFET_0402-3L_A1]  65.41 7.24 270 top
Q6  CSD25481F4  [MOSFET_0402-3L_A1]  81.91 6.1 90 top
Q17  MMBT3904  [SOT23-3L_1P9_2P9X1P3]  19.43 55.12 270 top
Q41  MMBT3904  [SOT23-3L_1P9_2P9X1P3]  35.69 63.5 90 bottom
R1  2.2K  [0402]  23.5 89.92 270 top
R3  100K  [0402]  24.26 84.33 180 top
R4  10K  [0402]  27.05 91.31 90 top
R5  4.7K  [0402]  15.88 92.69 0 top
R6  1K  [0402]  16.38 80.77 180 top
R7  1K  [0402]  26.54 82.3 0 top
R8  100K  [0402]  14.48 73.41 180 top
R9  100K  [0402]  14.48 74.55 0 top
R10  100K  [0402]  53.09 62.1 90 top
R11  10E  [0402]  35.56 63.37 90 top
R12  0E  [0402]  39.24 64.13 90 bottom
R13  10K  [0402]  38.61 70.1 270 top
R14  15K  [0402]  39.75 70.1 270 top
R15  100K  [0402]  51.94 62.1 270 top
R16  1M  [0402]  54.74 63.12 90 top
R17  1M  [0402]  57.02 58.29 90 top
R18  100K  [0402]  55.63 65.91 270 top
R19  300K  [0402]  54.48 65.91 270 top
R20  100K  [0402]  93.98 71.12 180 top
R21  0E  [0402]  45.59 66.04 90 bottom
R22  100K  [0402]  46.74 64.39 270 bottom
R23  100K  [0402]  57.02 65.91 270 top
R24  29.4K  [0402]  46.74 66.04 270 bottom
R25  2.2K  [0402]  42.93 37.72 270 bottom
R26  100K  [0402]  41.91 47.88 90 top
R27  100K  [0402]  52.2 67.69 270 top
R28  10K  [0402]  51.05 65.91 90 top
R31  0E  [0402]  32 38.48 270 top
R32  0E  [0402]  17.65 75.56 90 bottom
R33  0E  [0402]  91.19 21.08 270 top
R34  100K  [0402]  89.41 21.97 270 top
R35  100K  [0402]  88.9 20.19 270 top
R36  10K  [0402]  29.84 86.74 0 bottom
R37  100K  [0402]  90.04 20.19 270 top
R58  10K  [0402]  88.14 40.39 0 top
R60  10K  [0402]  88.14 39.24 0 top
R62  240E  [0402]  88.14 38.1 0 top
R63  240E  [0402]  88.14 36.96 180 top
R64  10K  [0402]  80.39 34.54 270 bottom
R65  240E  [0402]  66.42 45.47 90 bottom
R66  1.5K  [0402]  65.91 51.44 90 bottom
R67  100E  [0402]  81.28 39.12 90 bottom
R68  1.5K  [0402]  67.06 51.44 270 bottom
R69  0E  [0402]  51.44 35.69 90 bottom
R70  0E  [0402]  51.03 36.09 0 bottom
R71  22E  [0402]  66.55 30.99 0 top
R72  10K  [0402]  87 28.58 270 bottom
R73  10K  [0402]  89.66 30.35 270 bottom
R74  10K  [0402]  90.93 30.35 270 bottom
R75  10K  [0402]  84.46 30.35 270 bottom
R76  10K  [0402]  85.72 30.35 270 bottom
R77  10K  [0402]  79.88 19.18 90 bottom
R78  33E  [0402]  43.43 9.27 270 bottom
R79  33E  [0402]  42.8 11.3 270 bottom
R80  33E  [0402]  43.94 11.3 270 bottom
R81  22E  [0402]  70.74 32.38 0 top
R82  22E  [0402]  88.14 28.58 270 bottom
R83  33E  [0402]  43.56 32.89 90 bottom
R84  33E  [0402]  42.42 32.89 90 bottom
R85  33E  [0402]  44.7 32.89 90 bottom
R86  10K  [0402]  55.12 76.07 180 bottom
R87  0E  [0402]  78.74 19.18 270 bottom
R88  0E  [0402]  54.48 67.56 270 top
R89  0E  [0402]  45.21 35.94 0 top
R90  0E  [0402]  45.21 34.8 0 top
R94  47K  [0402]  66.29 21.72 0 top
R95  47K  [0402]  66.29 24 0 top
R96  47K  [0402]  66.29 25.15 0 top
R97  47K  [0402]  66.29 19.43 0 top
R98  47K  [0402]  66.29 20.57 0 top
R99  47K  [0402]  66.29 22.86 0 top
R100  47K  [0402]  66.29 26.29 0 top
R101  47K  [0402]  68.07 28.58 0 top
R102  10K  [0402]  66.42 17.14 0 top
R103  10K  [0402]  76.84 21.59 270 bottom
R104  10K  [0402]  67.69 27.18 180 bottom
R105  22E  [0402]  84.46 28.58 270 bottom
R106  22E  [0402]  85.72 28.58 270 bottom
R107  22E  [0402]  89.66 28.58 270 bottom
R108  22E  [0402]  90.93 28.58 270 bottom
R109  220E  [0402]  33.15 11.18 90 top
R110  2.2K  [0402]  34.29 11.18 270 top
R112  33E  [0402]  47.75 17.27 90 top
R113  1.5K  [0402]  45.34 20.07 180 top
R114  2.2K  [0402]  49.02 9.91 270 bottom
R115  2.2K  [0402]  50.93 31.24 90 bottom
R116  220E  [0402]  14.35 36.45 270 top
R117  33E  [0402]  46.61 17.27 90 top
R118  33E  [0402]  49.02 11.68 270 bottom
R119  33E  [0402]  52.45 11.68 90 bottom
R120  220E  [0402]  22.73 36.45 90 top
R121  0E  [0402]  14.73 22.73 270 bottom
R122  33E  [0402]  49.78 29.46 90 bottom
R123  33E  [0402]  48.64 29.46 90 bottom
R124  220E  [0402]  32.89 34.67 270 top
R125  33E  [0402]  50.93 29.46 90 bottom
R126  33E  [0402]  53.34 29.46 270 bottom
R127  100K  [0402]  46.86 18.92 0 top
R128  2.2K  [0402]  34.42 34.67 90 top
R129  4.87K  [0402]  35.31 20.96 180 bottom
R130  10K  [0402]  55.24 13.21 270 bottom
R131  220E  [0402]  17.78 11.94 270 bottom
R132  0E  [0402]  55.5 20.57 180 bottom
R133  100K  [0402]  56.39 13.21 270 bottom
R134  220E  [0402]  19.68 11.94 270 bottom
R135  0E  [0402]  24.51 36.45 270 top
R136  0E  [0402]  80.01 60.45 90 bottom
R137  4.7K  [0402]  70.61 62.74 90 top
R138  4.7K  [0402]  69.47 62.74 90 top
R139  0E  [0402]  81.15 60.45 90 bottom
R140  10K  [0402]  72.64 59.05 90 top
R141  10K  [0402]  73.79 59.05 90 top
R142  10K  [0402]  70.1 59.05 90 top
R143  10K  [0402]  68.33 75.69 270 bottom
R144  10K  [0402]  71.88 62.74 270 top
R145  10K  [0402]  70.36 60.96 0 top
R146  10K  [0402]  71.25 59.05 270 top
R147  10K  [0402]  68.58 73.41 270 bottom
R148  1M  [0402]  77.09 71.81 270 top
R149  10K  [0402]  79.38 63.25 0 top
R150  470E  [0402]  90.17 94.62 90 top
R151  470E  [0402]  71.25 94.87 90 top
R152  10K  [0402]  74.55 62.87 270 top
R153  470E  [0402]  67.82 94.87 90 top
R154  10K  [0402]  67.18 62.74 270 top
R155  0E  [0402]  63.75 63.88 0 top
R156  0E  [0402]  63.75 66.17 0 top
R157  470E  [0402]  48.77 94.74 90 top
R158  470E  [0402]  35.94 94.87 90 top
R159  0E  [0402]  63.88 70.49 0 top
R160  0E  [0402]  63.88 72.77 0 top
R161  10K  [0402]  79.38 65.53 180 top
R162  10K  [0402]  79.38 64.39 180 top
R163  10K  [0402]  79.38 67.82 180 top
R164  10K  [0402]  57.02 68.2 180 bottom
R165  10K  [0402]  79.38 66.68 180 top
R166  10K  [0402]  57.02 67.06 180 bottom
R167  10K  [0402]  17.53 49.15 270 bottom
R168  0E  [0402]  10.41 42.29 90 bottom
R169  0E  [0402]  16.26 49.15 90 bottom
R170  0E  [0402]  15.11 49.15 90 bottom
R171  27E  [0402]  10.67 39.75 0 top
R172  27E  [0402]  10.67 40.89 0 top
R173  10K  [0402]  8.51 38.61 0 top
R174  10K  [0402]  20.45 43.56 180 bottom
R175  4.7K  [0402]  11.18 49.15 270 bottom
R176  1K  [0402]  22.86 40.64 0 top
R177  1K  [0402]  7.62 46.74 270 top
R178  0E  [0402]  2.79 45.85 90 top
R179  10K  [0402]  12.32 49.15 270 bottom
R180  4.7K  [0402]  9.27 42.29 270 bottom
R181  10K  [0402]  26.8 51.44 180 bottom
R182  10K  [0402]  26.8 49.91 180 bottom
R183  10mE  [0603]  47.75 69.22 0 top
R184  10mE  [0603]  49.53 47.88 0 top
R185  10K  [0402]  31.5 72.52 180 bottom
R186  10mE  [0603]  43.94 46.1 270 top
R187  10mE  [0805]  32.89 57.28 0 top
R188  10mE  [0805]  38.73 47.24 90 top
R189  10mE  [0805]  35.31 84.33 270 top
R190  0E  [0402]  59.56 5.33 270 top
R191  0E  [0402]  67.44 6.35 270 top
R192  100K  [0402]  60.96 6.86 0 top
R193  100K  [0402]  63.88 7.11 90 top
R194  10K  [0402]  59.05 7.49 90 bottom
R195  10K  [0402]  81.41 10.03 270 bottom
R196  0E  [0402]  78.99 10.03 270 bottom
R197  10K  [0402]  80.26 10.03 90 bottom
R198  33E  [0402]  57.91 7.49 270 bottom
R199  0E  [0402]  60.96 20.83 0 bottom
R200  33E  [0402]  55.63 7.62 270 bottom
R201  0E  [0402]  60.96 19.68 0 bottom
R202  33E  [0402]  54.48 7.49 270 bottom
R203  33E  [0402]  56.77 7.62 270 bottom
